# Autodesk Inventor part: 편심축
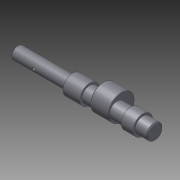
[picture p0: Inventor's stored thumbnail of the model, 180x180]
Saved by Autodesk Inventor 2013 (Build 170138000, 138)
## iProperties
Company: 한국ATC센터
Created: 2015-12
Part Number: 편심축
Document SubType Name: Modeling
Designer: mdu
Density: 7.86 g/cm^3
Mass: 222.98 g
Surface Area: 83.5889 cm^2
Volume: 28.3689 cm^3
Material: 강철, 연강
Author: mdu
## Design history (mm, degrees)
sketch "스케치1"
  geometry: L1 (-86, 0)-(86, 0); L2 (-86, 0)-(-86, 6); L3 (-86, 6)-(-32, 6); L4 (-32, 6)-(-32, 9.5); L5 (-32, 9.5)-(-15.5, 9.5); L6 (-15.5, 9.5)-(-15.5, 7.5); L7 (-15.5, 7.5)-(48, 7.5); L8 (86, 6)-(86, 0); L9 (36, 7.5)-(36, 9.5); L10 (36, 9.5)-(24.5, 9.5); L11 (24.5, 9.5)-(24.5, 7.5); L12 (48, 7.5)-(48, 6); L13 (48, 6)-(86, 6); 2 further points
  constraints: 26 end point, 6 parallel, 6 perpendicular, 2 point on line, 1 coincident, 1 horizontal, 1 midpoint
  dimensions: "d1" = 12 diameter of L3 L1; "d2" = 15 diameter of L7 L1; "d4" = 16.5 distance of L4.end L5.end; "d5" = 19 diameter of L5 L1; "d24" = 11.5 distance of L9.end L10.end; "d25" = 19 diameter of L10 L1; "d27" = 40 distance between parallel lines of L11 L6; "d28" = 54 distance of L2.end L3.end; "d29" = 50 distance between parallel lines of L8 L9; "d41" = 38 distance between parallel lines of L8 L12; "d42" = 12 diameter of L13 L1
revolve "회전1" stored, may be unused: angle "d6" = 90 deg
node "작업 평면1"
sketch "스케치2"
  geometry: C1 r 7.5 at (0, 0) reference; C2 r 12.5 at (0, 4.5); 1 further point
  constraints: 1 centre point, 1 vertical alignment
  dimensions: "d8" = 4.5 distance of point (0, 0) C2.centre; "d9" = 25 diameter of C2
extrude "돌출1" join sketch "스케치2" distance "d10" = 18; taper "d11" = 0 deg
chamfer "모따기1" distance "d12" = 1; stored, may be unused: second distance "d13" = 2, angle "d14" = 45 deg
chamfer "모따기2" distance "d15" = 0.5; stored, may be unused: second distance "d16" = 2, angle "d17" = 45 deg
node "작업 평면2"
sketch "스케치3"
  geometry: L1 (4, -2)-(18, -2); L2 (18, 2)-(4, 2); L3 (27, 5)-(27, -5) reference; A1 r 2 centre (18, 0) between (18, -2) and (18, 2); A2 r 2 centre (4, 0) between (4, 2) and (4, -2); 2 further points
  constraints: 4 end point, 4 point on circle, 4 tangent, 2 centre point, 1 horizontal, 1 horizontal alignment, 1 midpoint, 1 parallel
  dimensions: "d18" = 7 distance edge to line of A1 L3; "d19" = 4 distance between parallel lines of L2 L1; "d20" = 18 dimension on A1 A2
extrude "돌출2" cut sketch "스케치3" distance "d21" = 2.5; taper "d22" = 0 deg
revolve "회전2" stored, may be unused: angle "d26" = 90 deg
node "작업 평면3"
sketch "스케치4"
  geometry: L1 (44, 5)-(44, -5) reference; 2 further points
  constraints: 1 horizontal alignment
  dimensions: "d30" = 12 distance from line of point (32, 0) L1
hole "구멍1" sketch "스케치4" at (32, 0) diameter "d31" = 6; stored, may be unused: countersink angle "d35" = 90 deg, drill point angle "d37" = 118 deg; dims "d32" = 6, "d33" = 14, "d34" = 3, "d36" = 8
node "작업 평면4"
sketch "스케치5"
  geometry: C1 r 3 at (32, 0) reference; C2 r 8 at (32, 0); 2 further points
  constraints: 1 centre point, 1 coincident, 1 other
  dimensions: "d38" = 16 diameter of C2
extrude "돌출3" cut sketch "스케치5" distance "d39" = 3; taper "d40" = 0 deg
sketch "스케치6"
  geometry: L1 (-85, -6)-(-32, -6) reference; L2 (-86, -5)-(-86, 5) reference; L3 (-85, 6)-(-32, 6) reference; L4 (-64, 6)-(-64, -6); L5 (-64, -6)-(-62.5, -6); L6 (-64, -4.5)-(-62.5, -6); L7 (-64, -6)-(-64, -4.5); 2 further points
  constraints: 8 end point, 4 point on line, 2 perpendicular, 1 coincident
  dimensions: "d43" = 22 distance between parallel lines of L4 L2; "d44" = 45 deg angle of L6 L7; "d45" = 3 diameter of L5.end L4
revolve "회전3" stored, may be unused: angle "d46" = 90 deg
node "작업점1"
chamfer "모따기3" distance "d47" = 0.5; stored, may be unused: second distance "d48" = 2, angle "d49" = 45 deg
sketch "스케치7"
  geometry: C1 r 7.5 at (0, 0) reference; 1 further point
extrude "돌출4" cut sketch "스케치7" stored distance "d50" = 10; taper "d51" = 0 deg
chamfer "모따기4" distance "d52" = 1; stored, may be unused: second distance "d53" = 2, angle "d54" = 45 deg
node "작업 평면5"
hole "구멍2" diameter "d63" = 4.917; stored, may be unused: countersink angle "d67" = 90 deg, drill point angle "d69" = 118 deg; dims "d64" = 12, "d65" = 4, "d66" = 2, "d68" = 15, "d72" = 10, "d73" = 10
node "솔리드1"
node "투영된 루프1"
other parameters: "d7" = 8.5
